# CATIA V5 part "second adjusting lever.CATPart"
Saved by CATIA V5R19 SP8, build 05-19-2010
Part number: second adjusting lever
Bounding box of the stored display mesh (mm): x -20.399 to 68.888, y 0 to 72.4, z 8.304 to 145.727
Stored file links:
  G:\EU_thinkMotion\CFAO_2010\MMS_groupe1\MMS_groupe1\A reprendre\gduval\CFAO kinematic ok\second adjusting lever.CATPart
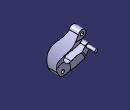
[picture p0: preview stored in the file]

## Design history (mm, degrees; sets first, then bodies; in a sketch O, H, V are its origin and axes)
Body1 (main body)
  Point1 to Point3: stored without definition
  Sketch1 on zx-plane, origin (0, 0, 0), H (-1, 0, 0), V (0, 0, 1)
    spline S1 through (-43.8621, 136.7842) (-57.7396, 113.1323) (-66.5432, 85.312) (-68.6561, 52.2095) (-66.5432, 36.7146) (-62.6843, 24.2934)
    spline S2 through (-62.6843, 24.2934) (-59.2484, 17.0681) (-51.9256, 9.8782) (-48.1977, 8.5468) (-41.8069, 8.5468) (-33.1526, 9.8782) (-20.9036, 12.8074) (-9.8528, 17.8669) (-1.7302, 26.9208) (4.5275, 37.5725) (11.1849, 48.2241) (16.5105, 56.8786) (20.0266, 63.023)
    arc A1 centre (12.169, 65.472) radius 8.2304 from (20.0266, 63.023) to (5.0269, 69.5624) ccw
    point P1 (20.0266, 63.023)
    point P2 (12.169, 65.472)
    reference projected point E1 (12.169, 65.472) from Point1
    line L1 (5.0269, 69.5624) -> (-22.3198, 35.5576)
    point P4 (-22.3198, 35.5576)
    spline S3 through (-22.3198, 35.5576) (-26.536, 33.3714) (-36.3737, 35.5576) (-41.9952, 41.6477) (-45.7428, 52.2095) (-46.5236, 63.023) (-46.5236, 73.1915) (-43.0882, 93.8042) (-37.1543, 110.0445) (-29.7546, 123.2378)
    arc A2 centre (-32.689, 134.301) radius 11.4457 from (-29.7546, 123.2378) to (-43.8621, 136.7842) ccw
    point P5 (-29.7546, 123.2378)
    point P6 (-32.689, 134.301)
    point P7 (-43.8621, 136.7842)
    reference projected point E2 (-32.689, 134.301) from Point2
    point P8 (-62.6843, 24.2934)
    point P9 (-62.6843, 24.2934)
    point P10 (20.0266, 63.023)
    point P11 (-22.3198, 35.5576)
    point P12 (-29.7546, 123.2378)
    point P13 (-43.8621, 136.7842)
    coincidence: P8 P9, P10 P1, P2 E1, P11 P4, P12 P5, P7 P13, E2 P6
  Plane1: stored without definition
  Plane2: stored without definition
  Pad1: profile Sketch1, direction (0, 1, 0), up to Plane1
  DatumPoint1
  Line1: stored without definition
  Sketch2 on yz-plane, origin (0, 0, 0), H (0, 1, 0), V (0, 0, 1)
    line L1 (44.3, 156.5746) -> (44.3, 123.2378)
    point P2 (44.3, 123.2378)
    reference projected point E1 (44.3, 134.301) from vertex of DatumPoint1
    reference projected line E2 (0, 123.2378) -> (72.4, 123.2378) from edge [face of Pad1 from Sketch1.A2 | face of Pad1 from Sketch1.S3]
    spline S1 through (44.3, 123.2378) (36.1831, 107.3576) (25.2384, 93.2225) (14.3847, 76.4181) (0, 28.4382)
    line L2 (44.3, 156.5746) -> (0, 156.5746)
    point P3 (0, 156.5746)
    line L3 (0, 156.5746) -> (0, 28.4382)
    point P4 (0, 28.4382)
    point P5 (44.3, 123.2378)
    point P6 (0, 28.4382)
    vertical: L1 V, L3 V
    coincidence: L1 E1, P2 E2, P5 P2, P6 V, P3 V, P6 P4
    horizontal: L2 H
  Groove1: profile Sketch2, axis Line1, angle 70, second angle 30
  DatumPoint2
  Plane3: type Angle, RefPlane yz-plane, Direction Line1, Angle 10
  Sketch3 on Plane3, origin (41.8202, 0, -7.374), H (0, 1, 0), V (0.1736, 0, 0.9848)
    point P1 (28.1, 28.3548)
    spline S1 through (28.1, 51.6557) (35.5626, 72.2616) (46.1318, 86.5341) (61.7359, 106.0947) (71.933, 125.63) (72.4, 129.8278)
    reference intersected line E1 (72.4, 113.0355) -> (72.4, 15.9203) from end face of Pad1
    line L1 (72.4, 129.8278) -> (86.3936, 129.8278)
    point P2 (72.4, 129.8278)
    line L2 (86.3936, 129.8278) -> (86.3936, 28.3548)
    point P4 (86.3936, 28.3548)
    point P5 (86.3936, 28.3548)
    line L3 (28.1, 28.3548) -> (86.3936, 28.3548)
    reference projected line E2 (0, 28.3548) -> (28.1, 28.3548) from Line1
    reference projected point E3 (28.1, 28.3548) from DatumPoint2
    line L4 (28.1, 51.6557) -> (28.1, 28.3548)
    point P6 (28.1, 51.6557)
    point P7 (28.1, 51.6557)
    point P8 (72.4, 129.8278)
    coincidence: E1 P8, P8 P2, P5 P4, L3 E2, P1 E3, P7 P6
    horizontal: L1 H, L3 H
    vertical: L2 V, L4 V
  Groove2: profile Sketch3, axis Sketch3.L3, angle 300, second angle 60
  Sketch4 on yz-plane, origin (0, 0, 0), H (0, 1, 0), V (0, 0, 1)
    line L1 (44.3, 74.571) -> (44.3, 17.6328)
    point P2 (44.3, 17.6328)
    reference projected point E1 (44.3, 65.472) from Point1
    line L2 (44.3, 74.571) -> (66.6373, 74.571)
    line L3 (66.6373, 74.571) -> (66.6373, 23.6542)
    point P5 (44.3, 17.6328)
    line L4 (66.6373, 23.6542) -> (44.3, 17.6328)
    vertical: L1 V, L3 V
    coincidence: E1 L1, P5 P2
    horizontal: L2 H
  Pocket1: profile Sketch4, direction (-1, 0, 0), length 25, mirrored extent
  Sketch5 on Plane3, origin (41.8202, 0, -7.374), H (0, 1, 0), V (0.1736, 0, 0.9848)
    spline S1 through (18.9681, 107.3872) (7.6682, 88.4851) (1.1355, 66.8894) (0, 50.7467)
    reference projected curve E1 from edge [face of Pad1 from Sketch1.S1 | face of Groove1 from Sketch2.S1]
    reference projected curve E2 from edge [face of Pad1 from Sketch1.S1 | face of Groove1 from Sketch2.S1]
    line L1 (18.9681, 107.3872) -> (-16.9931, 113.5938)
    point P1 (18.9681, 107.3872)
    line L2 (-16.9931, 113.5938) -> (-14.1663, 52.5929)
    line L3 (-14.1663, 52.5929) -> (0, 50.7467)
    point P4 (0, 50.7467)
    point P5 (0, 50.7467)
    point P6 (18.9681, 107.3872)
    coincidence: P5 V, P6 E1, P6 P1, P5 P4
    tangency: S1 E2
  Groove3: profile Sketch5, axis Line1, angle 120, second angle 140
  Fillet1: radius 5, on edge [face of Groove2 from Sketch3.S1 | face of Pocket1 from Sketch4.L1]
  Sketch6 on face of Groove2 from Sketch3.L4, origin (46.744, 28.1, 20.55), H (1, 0, 0), V (0, 0, -1)
    point P1 (0, 0)
    reference projected point E1 (0, 0) from vertex of DatumPoint2
    coincidence: E1 P1
  Hole1: placed by Sketch6, at (46.744, 28.1, 20.55) direction (0, -1, 0), diameter 10, through (limit type 6)
  Sketch7 on end face of Pad1, origin (32.689, 72.4, 134.301), H (1, 0, 0), V (0, 0, -1)
    point P1 (0, 0)
    reference projected point E1 (0, 0) from Point2
    coincidence: E1 P1
  Hole2: placed by Sketch7, at (32.689, 72.4, 134.301) direction (0, -1, 0), diameter 10, through (limit type 6)
  Sketch8 on face of Pocket1 from Sketch4.L1, origin (0, 44.3, 0), H (-1, 0, 0), V (0, 0, 1)
    circle A1 centre (12.169, 65.472) radius 5
    point P1 (12.169, 65.472)
    reference projected point E1 (12.169, 65.472) from Point1
    radius A1 = 5
    coincidence: P1 E1
  Pad2: profile Sketch8, direction (0, 1, 0), length 25.86
  Line2: type PtDir, RefPoint Point1, Direction Plane1, Start 30, End -30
